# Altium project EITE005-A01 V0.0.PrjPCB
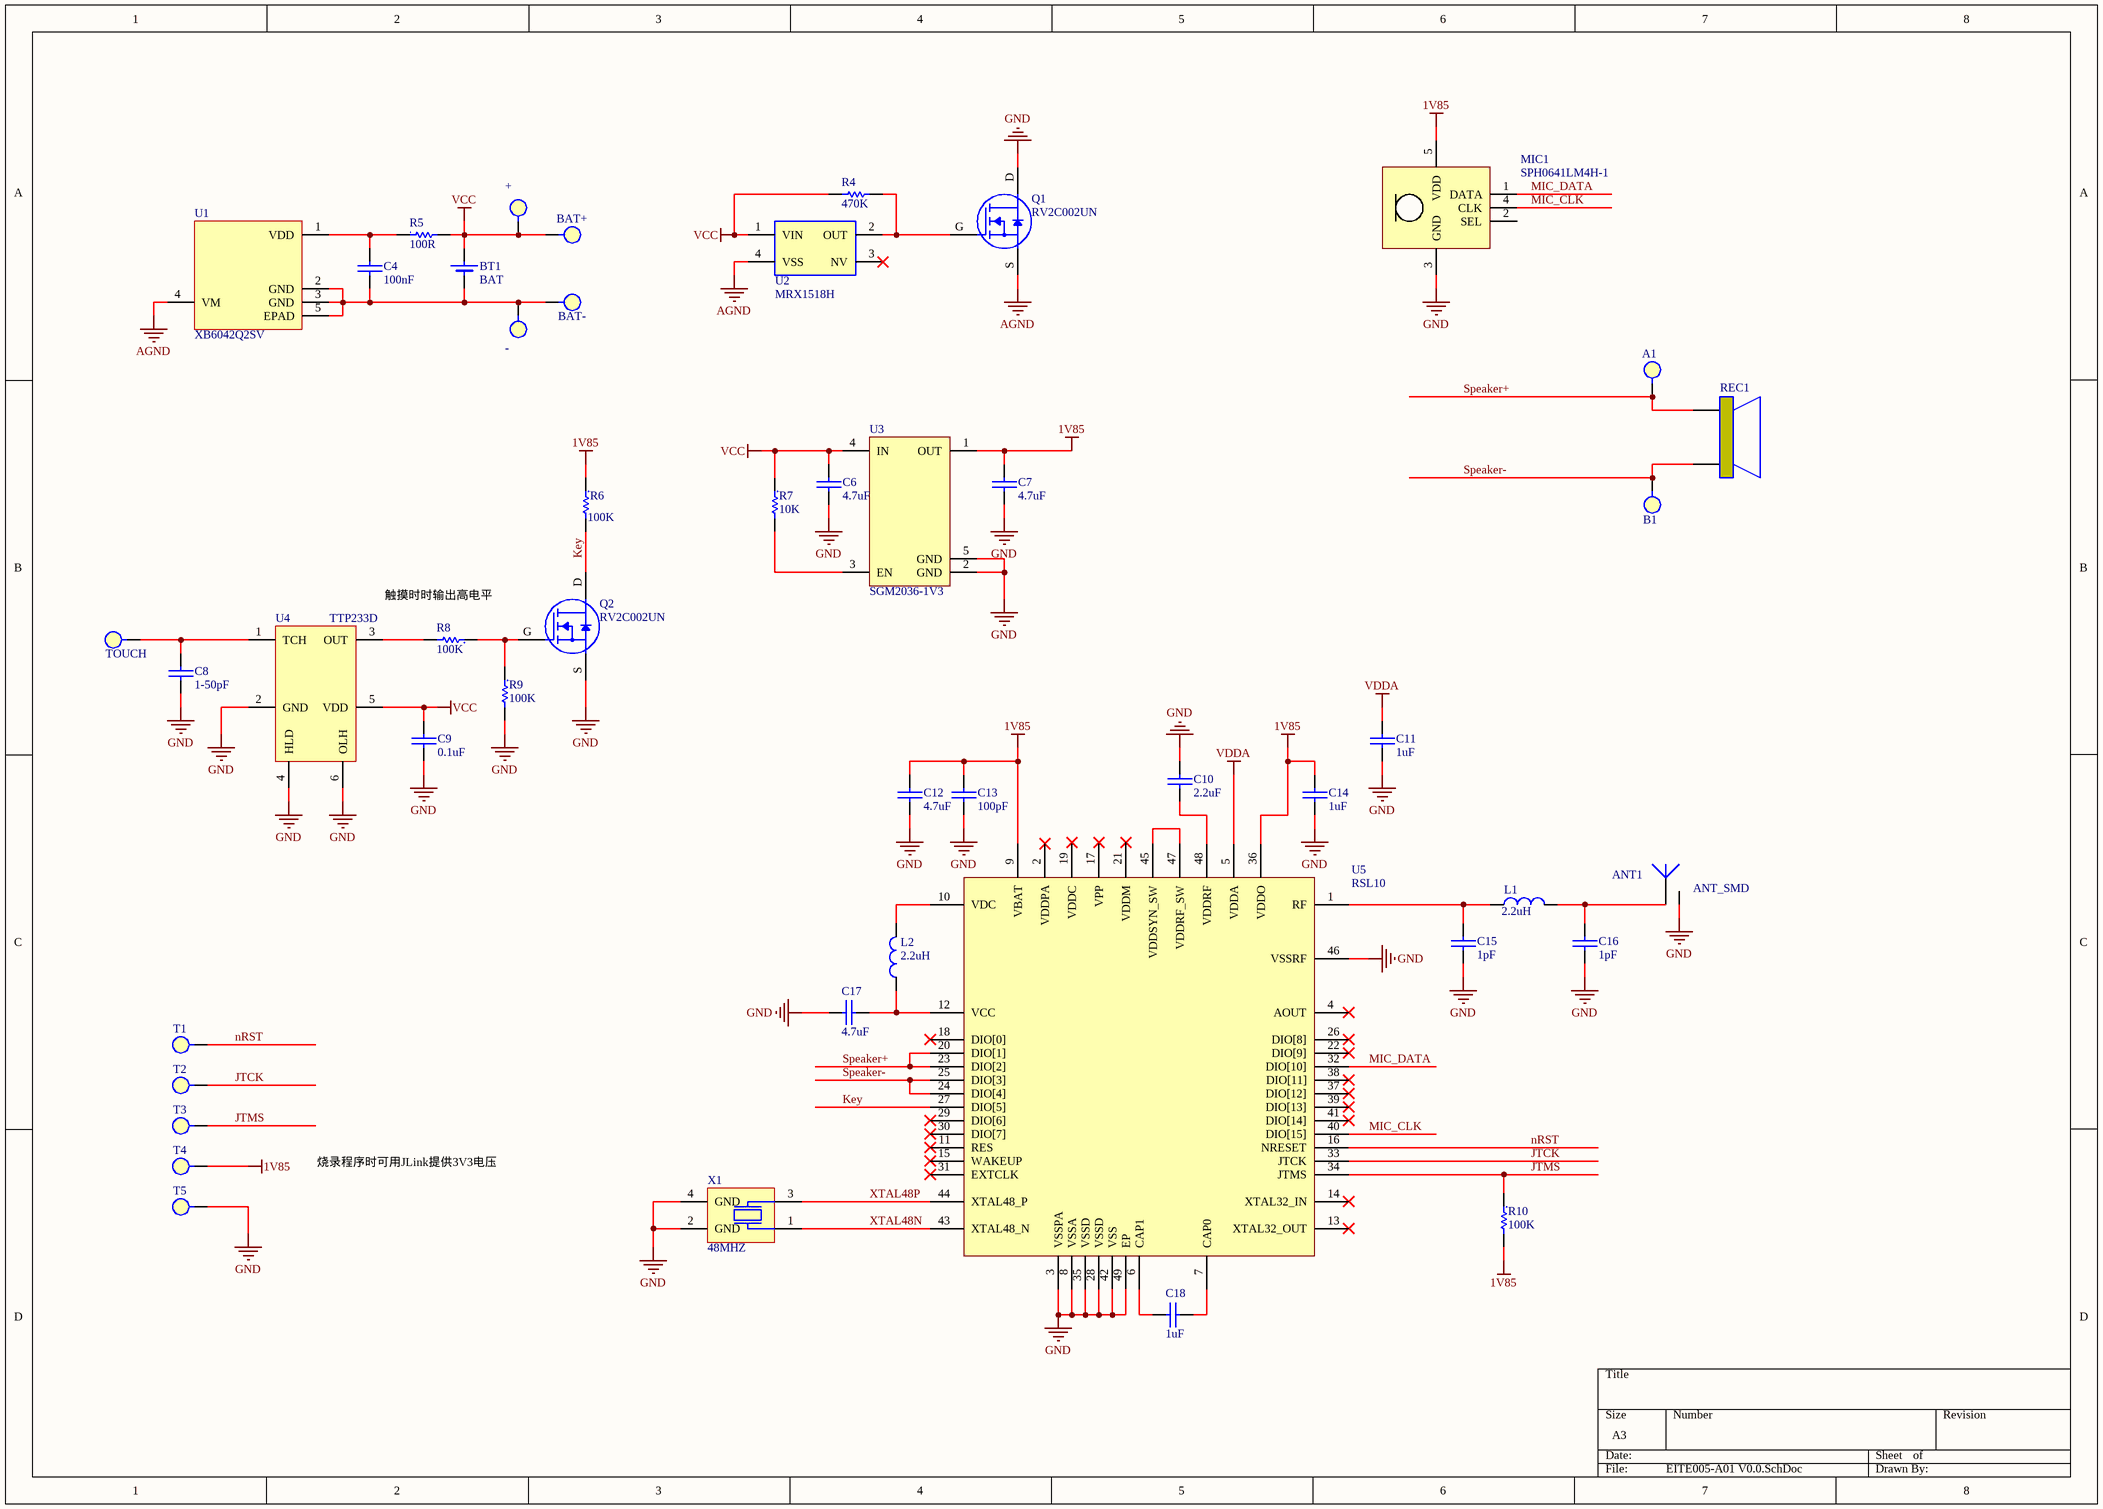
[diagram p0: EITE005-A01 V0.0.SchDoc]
1 sheet, 47 parts. Net scope: global (net labels, ports and power ports of the same name join across sheets).
Board file: EITE005-A01 V0.0.PcbDoc

## Sheet EITE005-A01 V0.0.SchDoc
size A3

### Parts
+  (no value)  [PAD_1]
-  (no value)  [PAD_1]
A1  PAD  [PAD0608]  (value not drawn)
ANT1  ANT_SMD  [ANT2012_2.4G_1]
B1  PAD  [PAD0608]  (value not drawn)
BAT+  (no value)  [PAD_1]
BAT-  (no value)  [PAD_1]
BT1  BAT  [P13]
C4  100nF  [0201-C]
C6  4.7uF  [0201-C]
C7  4.7uF  [0201-C]
C8  1-50pF  [0201-C]
C9  0.1uF  [0201-C]
C10  2.2uF  [0201-C]
C11  1uF  [0201-C]
C12  4.7uF  [0201-C]
C13  100pF  [0201-C]
C14  1uF  [0201-C]
C15  1pF  [0201-C]
C16  1pF  [0201-C]
C17  4.7uF  [0201-C]
C18  1uF  [0201-C]
L1  2.2uH  [0201]
L2  2.2uH  [L_0603]
MIC1  SPH0641LM4H-1  [SPH0641LM4H-1]
Q1  RV2C002UN  [DFN1006]
Q2  RV2C002UN  [DFN1006]
R4  470K  [0201]
R5  100R  [0201-R]
R6  100K  [0201-R]
R7  10K  [0201-R]
R8  100K  [0201-R]
R9  100K  [0201-R]
R10  100K  [0201-R]
REC1  (no value)
T1  (no value)  [PAD06]
T2  (no value)  [PAD06]
T3  (no value)  [PAD06]
T4  (no value)  [PAD06]
T5  (no value)  [PAD06]
TOUCH  (no value)  [PAD_1]
U1  XB6042Q2SV  [UTDFN-4L_1]
U2  MRX1518H  [SON-4]
U3  SGM2036-1V3  [UTDFN-4L_1]
U4  TTP233D  [DNF-6]
U5  RSL10  [QFN-48 RSL10]
X1  48MHZ  [SMDP4P_2016]

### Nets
1V85: C7.1 C12.1 C13.1 C14.1 MIC1.5(VDD) R6.1 R10.2 T4.0 U3.1(OUT) U5.9(VBAT) U5.36(VDDO)
AGND: Q1.S U1.4(VM) U2.4(VSS)
GND: ANT1.2 C6.2 C7.2 C8.2 C9.2 C10.2 C11.2 C12.2 C13.2 C14.2 C15.2 C16.1 C17.1 MIC1.3(GND) Q1.D Q2.S R9.2 T5.0 U3.2(GND) U3.5(GND) U4.2(GND) U4.4(HLD) U4.6(OLH) U5.3(VSSPA) U5.8(VSSA) U5.28(VSSD) U5.35(VSSD) U5.42(VSS) U5.46(VSSRF) U5.49(EP) X1.2(GND) X1.4(GND)
VCC: +.0 BAT+.0 BT1.1(+) C6.1 C9.1 R4.2 R5.2 R7.1 U2.1(VIN) U3.4(IN) U4.5(VDD)
VDDA: C11.1 U5.5(VDDA)
JTCK: T2.0 U5.33(JTCK)
JTMS: R10.1 T3.0 U5.34(JTMS)
Key: Q2.D R6.2 U5.27(DIO[5])
MIC_CLK: MIC1.4(CLK) U5.40(DIO[15])
MIC_DATA: MIC1.1(DATA) U5.32(DIO[10])
nRST: T1.0 U5.16(NRESET)
Speaker+: A1.0 REC1.1 U5.20(DIO[1]) U5.23(DIO[2])
Speaker-: B1.0 REC1.2 U5.24(DIO[4]) U5.25(DIO[3])
XTAL48N: U5.43(XTAL48_N) X1.1
XTAL48P: U5.44(XTAL48_P) X1.3
Net-_0: -.0 BAT-.0 BT1.2(-) C4.2 U1.2(GND) U1.3(GND) U1.5(EPAD)
NetANT1_1: ANT1.1 C16.2 L1.2
NetC4_1: C4.1 R5.1 U1.1(VDD)
NetC8_1: C8.1 TOUCH.0 U4.1(TCH)
NetC10_1: C10.1 U5.48(VDDRF)
NetC15_1: C15.1 L1.1 U5.1(RF)
NetC17_2: C17.2 L2.1 U5.12(VCC)
NetC18_1: C18.1 U5.6(CAP1)
NetC18_2: C18.2 U5.7(CAP0)
NetL2_2: L2.2 U5.10(VDC)
NetQ1_G: Q1.G R4.1 U2.2(OUT)
NetQ2_G: Q2.G R8.1 R9.1
NetR7_2: R7.2 U3.3(EN)
NetR8_2: R8.2 U4.3(OUT)
NetU5_45: U5.45(VDDSYN_SW) U5.47(VDDRF_SW)

Not connected (* = marked no-connect by the designer): MIC1 2(SEL); U2 3(NV)*; U5 2(VDDPA)* 4(AOUT)* 11(RES)* 13(XTAL32_OUT)* 14(XTAL32_IN)* 15(WAKEUP)* 17(VPP) 18(DIO[0])* 19(VDDC) 21(VDDM)* 22(DIO[9])* 26(DIO[8])* 29(DIO[6])* 30(DIO[7])* 31(EXTCLK)* 37(DIO[12])* 38(DIO[11])* 39(DIO[13])* 41(DIO[14])*

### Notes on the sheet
- 触摸时时输出高电平
- 烧录程序时可用JLink提供3V3电压

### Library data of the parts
+ - BAT+ BAT- T1-T5 TOUCH = PAD
BT1 = BAT: Battery
C4 C6-C18 = CAP: Capacitor
L1 L2 = L
MIC1 = MIC
Q1 Q2 = MOS-N
R4 = Res1: Resistor; Value: 0R
R5-R10 = Res1: Resistor
REC1 = SPEK
U1 = XB6042
U3 = SGM2036
U5 = RSL10: RSL10 QFN-48
X1 = XT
